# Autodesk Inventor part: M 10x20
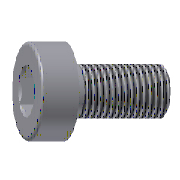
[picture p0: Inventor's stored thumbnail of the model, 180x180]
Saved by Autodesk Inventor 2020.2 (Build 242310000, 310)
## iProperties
Manager: www.cadconsulting.pl
Company: Fabian Stasiak CAD Consulting
Created: 2014-02
Part Number: M 10x20
Material: Stal, miękka
Description: Socket Head Cap Screw DIN 912 - 12.9
Document SubType Name: Modeling
Designer: F.Stasiak
Standard Revision: 1
Manufacturer: DME
Language: pl-PL
Size Designation: 10x20
Categories: <MemberInstance><Categories><Category DisplayName="Forma wtryskowa" InternalName="349578f2-f4d4-4954-8c09-8e99297a61c0" Mnemonic="MOLD"><Category DisplayName="C
Mass: 0.133121 g
Surface Area: 2.01441 cm^2
Volume: 0.133121 cm^3
Density: 7.85 g/cm^3
Appearance: Częściowo polerowana
Catalog Web Link: www.expertbooks.pl
IsCustomPart: 0
Author: F.Stasiak
Subject: Zbiór ćwiczeń. Autodesk Inventor 2020. Kurs Professional
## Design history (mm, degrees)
sketch "Sketch1"
  geometry: L1 (0, -26)-(0, 16) reference; L2 (4.619, 10)-(8, 10); L3 (8, 10)-(8, 0); L4 (8, 0)-(5, 0); L5 (5, 0)-(5, -20); L6 (5, -20)-(0, -20); L7 (0, 2.597)-(0, -20); L8 (0, 2.597)-(4, 5); L9 (4, 5)-(4, 9.381); L10 (4, 9.381)-(4.619, 10); 1 further point
  constraints: 18 end point, 4 vertical, 3 horizontal, 2 point on line
  dimensions: "d0" = 16 diameter of L3 L1 (= dk); "d1" = 10 distance between parallel lines of L4 L2 (= k); "d2" = 10 diameter of L5 L1 (= d); "d3" = 20 distance between parallel lines of L6 L4 (= L); "d4" = 59 deg angle of L1 L8; "d5" = 45 deg angle of L1 L10; "d6" = 8 diameter of L9 L1 (= sw); "d7" = 9.2376 diameter of L2.start L1 (= 1.1547 x sw); "d8" = 5 distance from line of L8.end L2 (= t)
revolve "Revolution1" sketch "Sketch1" stored, may be unused: angle "d44" = 90 deg
sketch "Sketch2"
  geometry: L1 (0, 4.619)-(4, 2.309); L2 (4, 2.309)-(4, -2.309); L3 (4, -2.309)-(0, -4.619); L4 (0, -4.619)-(-4, -2.309); L5 (-4, -2.309)-(-4, 2.309); L6 (-4, 2.309)-(0, 4.619); 3 further points
  constraints: 12 end point, 2 vertical alignment, 1 coincident, 14 other
extrude "Extrusion1" cut sketch "Sketch2" taper "d9" = 0 deg; stored distance "d45" = 10
thread "Thread1" dims "d10" = 20 (= b), "d11" = 0
chamfer "Chamfer1" distance "d12" = 0.75 (= 0.5 x P); stored, may be unused: second distance "d50" = 2, angle "d51" = 45 deg
fillet "Fillet1" dims "d13" = 0.75 (= 0.5 x P)
body "Solid1"
other parameters: "d" = 10 [user parameter; used in 1 equation term], "L" = 20 [user parameter; used in 1 equation term], "dk" = 16 [user parameter; used in 1 equation term], "b" = 20 [user parameter; used in 1 equation term], "k" = 10 [user parameter; used in 1 equation term], "sw" = 8 [user parameter; used in 2 equation terms], "t" = 5 [user parameter; used in 1 equation term], "P" = 1.5 [user parameter; used in 2 equation terms], "d14" = 0, "d15" = 0, "d55" = 0
